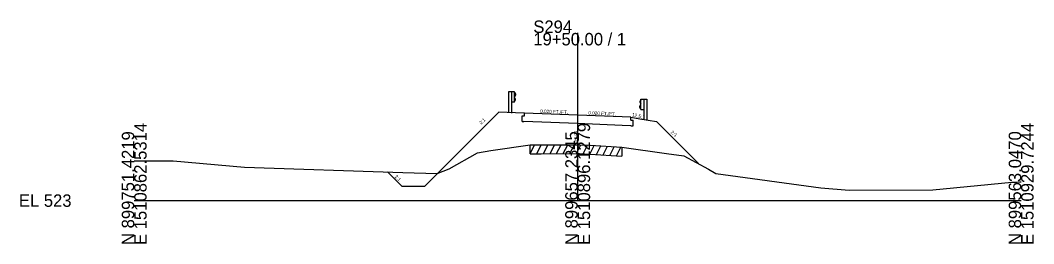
# Model space of a CAD drawing. Extents: x 974 to 2203, y -10 to 19041.
# Drawn here: x 974.3 to 1202.8, y 18990.3 to 19040.6 of the extents above; entities that cross this region are included whole.
import ezdxf

# ---------------------------------------------------------------- set-up
doc = ezdxf.new("R2010")
doc.units = 0
for name, color, linetype in [('RD_GPK_XS_Cell', 7, 'Continuous'), ('RD_XS_Base', 7, 'Continuous'), ('RD_XS_EarthShd', 7, 'Continuous'), ('RD_XS_ExGround', 7, 'Continuous'), ('RD_XS_ExPaveRet', 7, 'Continuous'), ('RD_XS_GR', 7, 'Continuous'), ('RD_XS_Pave', 7, 'Continuous'), ('RD_XS_TX_Elev_EX', 7, 'Continuous'), ('RD_XS_TX_Slope', 7, 'Continuous')]:
    doc.layers.add(name, color=color, linetype=linetype)

msp = doc.modelspace()

# ---------------------------------------------------------------- linework, layer by layer
at = {"layer": 'RD_GPK_XS_Cell'}
for p, q in [((1100, 19000), (1100, 19037.72)), ((1000, 19000), (1100, 19000)), ((1100, 19000), (1200, 19000))]:
    msp.add_line(p, q, dxfattribs=at)
at = {"layer": 'RD_XS_Base'}
for p, q in [((1087.5, 19017.81), (1087.5, 19019.08)), ((1087.5, 19019.08), (1088, 19019.06)), ((1088, 19019.06), (1088, 19019.7)), ((1112, 19018.1), (1112, 19018.74)), ((1087.5, 19017.81), (1087.89, 19017.8)), ((1089.89, 19017.72), (1087.89, 19017.8)), ((1099.95, 19017.32), (1089.89, 19017.72)), ((1110, 19016.91), (1099.95, 19017.32)), ((1112, 19016.83), (1110, 19016.91)), ((1112, 19018.1), (1112.5, 19018.08)), ((1112, 19016.83), (1112.5, 19016.81)), ((1112.5, 19016.81), (1112.5, 19018.08))]:
    msp.add_line(p, q, dxfattribs=at)
at = {"layer": 'RD_XS_EarthShd'}
for p, q in [((1065.43, 19003.17), (1082.2, 19019.93)), ((1086, 19019.78), (1082.2, 19019.93)), ((1088, 19019.7), (1086, 19019.78)), ((1112, 19018.74), (1114, 19018.41)), ((1114, 19018.41), (1117.75, 19017.78)), ((1127.22, 19008.31), (1117.75, 19017.78)), ((1060.43, 19003.17), (1057.15, 19006.45)), ((1065.43, 19003.17), (1060.43, 19003.17))]:
    msp.add_line(p, q, dxfattribs=at)
at = {"layer": 'RD_XS_ExGround'}
msp.add_lwpolyline([(1000, 19008.93), (1008.81, 19008.96), (1024.89, 19007.52), (1060.58, 19006.33), (1068.32, 19006.12), (1071.02, 19007.13), (1077.42, 19010.75), (1080.45, 19011.27), (1089.26, 19012.55), (1091.79, 19012.54), (1100, 19012.57), (1100.41, 19012.57), (1102.79, 19012.44), (1109.95, 19012.03), (1120, 19010.6), (1123.94, 19010.08), (1129.47, 19007.09), (1131.18, 19006.1), (1154.85, 19002.91), (1161.23, 19002.34), (1180.11, 19002.4), (1197.87, 19004.15), (1199.14, 19004.12), (1199.68, 19004.19), (1200, 19004.19)], dxfattribs=at)
at = {"layer": 'RD_XS_ExPaveRet'}
for p, q in [((1089.26, 19010.55), (1090.26, 19012.55)), ((1089.26, 19010.55), (1089.26, 19012.55)), ((1090.76, 19010.55), (1091.76, 19012.54)), ((1092.26, 19010.55), (1093.26, 19012.55)), ((1093.76, 19010.55), (1094.76, 19012.55)), ((1095.26, 19010.56), (1096.26, 19012.56)), ((1096.76, 19010.56), (1097.76, 19012.56)), ((1098.26, 19010.57), (1099.26, 19012.57)), ((1099.76, 19010.57), (1100.75, 19012.55)), ((1101.26, 19010.52), (1102.23, 19012.47)), ((1102.76, 19010.44), (1103.73, 19012.38)), ((1104.26, 19010.35), (1105.23, 19012.3)), ((1105.76, 19010.27), (1106.73, 19012.21)), ((1107.26, 19010.18), (1108.23, 19012.13)), ((1108.76, 19010.1), (1109.73, 19012.05)), ((1109.95, 19012.03), (1109.95, 19010.03)), ((1089.26, 19010.55), (1091.79, 19010.54)), ((1091.79, 19010.54), (1100, 19010.57)), ((1100, 19010.57), (1100.41, 19010.57)), ((1100.41, 19010.57), (1102.79, 19010.44)), ((1102.79, 19010.44), (1109.95, 19010.03))]:
    msp.add_line(p, q, dxfattribs=at)
at = {"layer": 'RD_XS_GR'}
for p, q in [((1084.41, 19024.47), (1084.41, 19019.71)), ((1085.08, 19024.47), (1084.41, 19024.47)), ((1085.08, 19024.47), (1085.08, 19019.68)), ((1085.74, 19024.47), (1085.08, 19024.47)), ((1085.74, 19022.14), (1085.74, 19024.47)), ((1085.74, 19024.33), (1086.01, 19023.93)), ((1086.01, 19023.83), (1085.74, 19023.43)), ((1086.01, 19022.79), (1085.74, 19023.19)), ((1086.01, 19023.93), (1086.01, 19023.83)), ((1085.74, 19022.14), (1085.08, 19022.14)), ((1085.74, 19022.29), (1086.01, 19022.69)), ((1086.01, 19022.69), (1086.01, 19022.79)), ((1114.27, 19022.68), (1114, 19022.28)), ((1114, 19022.28), (1114, 19022.18)), ((1114, 19022.18), (1114.27, 19021.78)), ((1114, 19021.14), (1114.27, 19021.54)), ((1114, 19021.04), (1114, 19021.14)), ((1114.27, 19020.64), (1114, 19021.04)), ((1114.27, 19022.82), (1114.94, 19022.82)), ((1114.27, 19020.49), (1114.27, 19022.82)), ((1114.94, 19022.82), (1114.94, 19018.17)), ((1114.94, 19022.82), (1115.6, 19022.82)), ((1115.6, 19022.82), (1115.6, 19018.06)), ((1114.27, 19020.49), (1114.94, 19020.49))]:
    msp.add_line(p, q, dxfattribs=at)
at = {"layer": 'RD_XS_Pave'}
for p, q in [((1090, 19019.62), (1088, 19019.7)), ((1100, 19019.22), (1090, 19019.62)), ((1110, 19018.82), (1100, 19019.22)), ((1112, 19018.74), (1110, 19018.82))]:
    msp.add_line(p, q, dxfattribs=at)

# ---------------------------------------------------------------- texts
at = {"layer": 'RD_GPK_XS_Cell'}
for s, p in [('S294', (1090, 19037.72)), ('19+50.00 / 1', (1090, 19034.92)), ('EL 523', (974, 18998.6))]:
    msp.add_text(s, height=2.8, dxfattribs=at).set_placement(p)
for s, p in [('E 1510862.5314', (1002.8, 18990)), ('E 1510896.1279', (1102.8, 18990)), ('E 1510929.7244', (1202.8, 18990)), ('N 899751.4219', (1000, 18990)), ('N 899657.2345', (1100, 18990)), ('N 899563.0470', (1200, 18990))]:
    msp.add_text(s, height=2.8, rotation=90, dxfattribs=at).set_placement(p)
at = {"layer": 'RD_XS_TX_Elev_EX'}
msp.add_text('529.29', height=0.75, rotation=90, dxfattribs=at).set_placement((1100, 19012.57))
at = {"layer": 'RD_XS_TX_Slope'}
for s, height, rotation, p in [('0.020 FT./FT.', 0.7518, 357.7673, (1091.53, 19019.75)), ('0.020 FT./FT.', 0.7518, 357.7673, (1102.39, 19019.36)), ('12.5:1', 0.778, 347.2489, (1112.17, 19018.99)), ('2:1', 0.778, 40.6589, (1078.18, 19017.08)), ('2:1', 0.778, 319.3411, (1120.92, 19015.24)), ('2:1', 0.778, 319.3411, (1058.64, 19005.27))]:
    msp.add_text(s, height=height, rotation=rotation, dxfattribs=at).set_placement(p)

doc.saveas('drawing.dxf')
